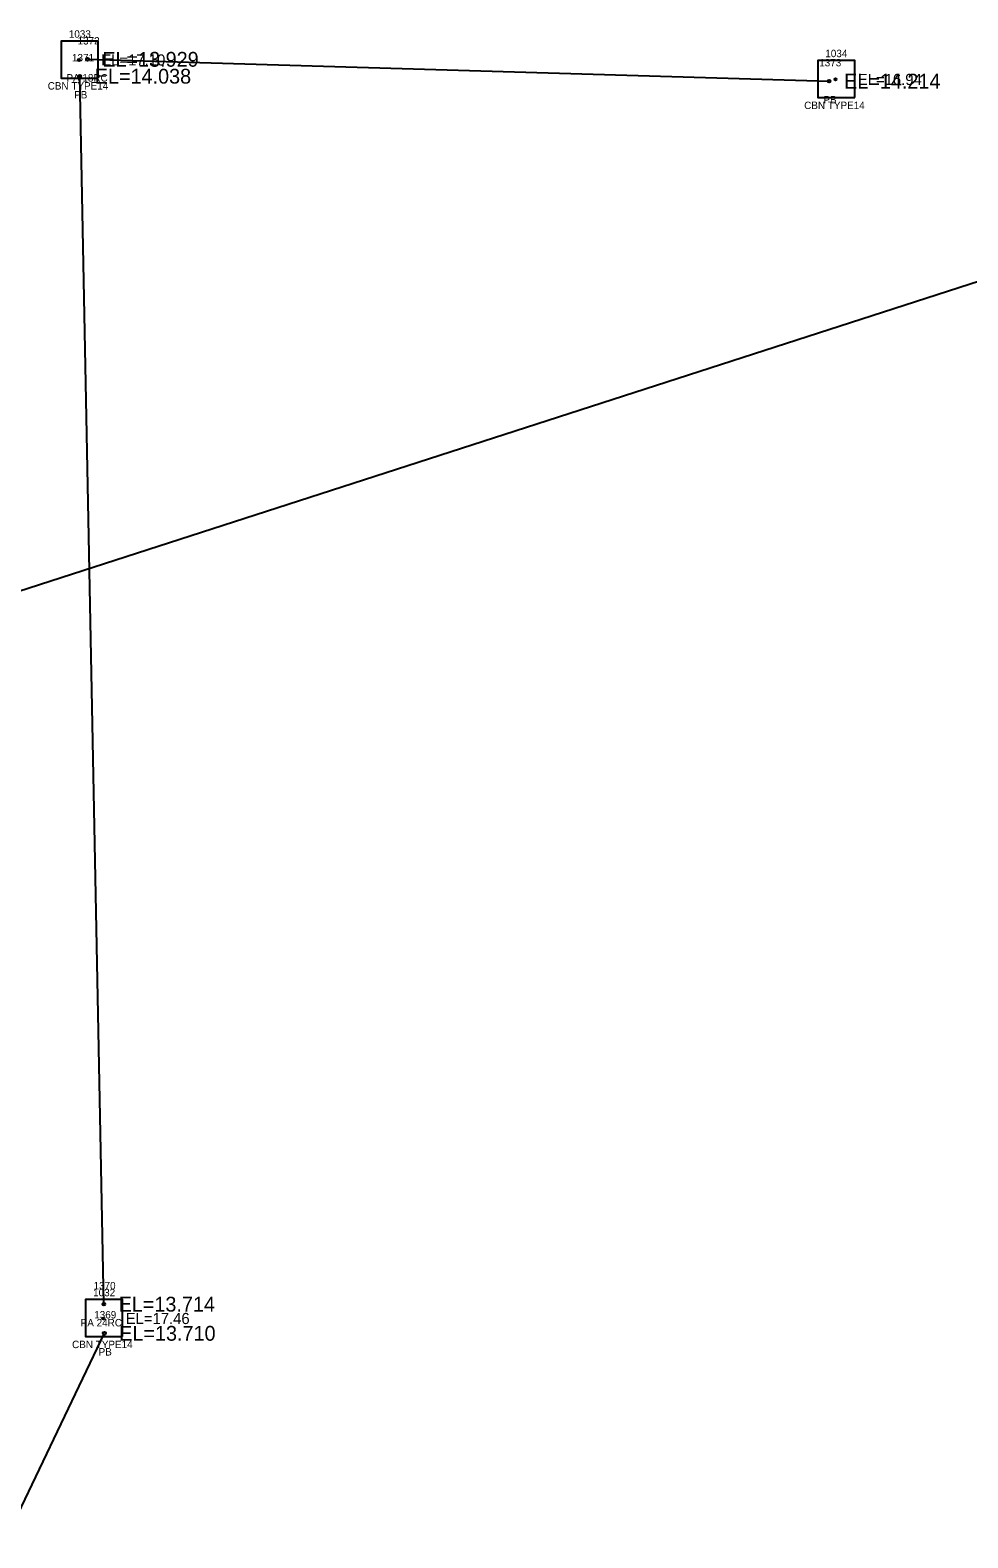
# Model space of a CAD drawing. Extents: x 2072307 to 2072993, y 127574 to 129736.
# Drawn here: x 2072496.8 to 2072623.4, y 129052.1 to 129255.6 of the extents above; entities that cross this region are included whole.
import ezdxf

# ---------------------------------------------------------------- set-up
doc = ezdxf.new("R2010")
doc.units = 0
for name, color, linetype in [('RD_EX_DR_Inlet', 7, 'Continuous'), ('RD_EX_DR_Inlet_txCode', 7, 'Continuous'), ('RD_EX_DR_Pipe', 7, 'Continuous'), ('RD_EX_DR_Pipe_txCode', 7, 'Continuous'), ('RD_EX_TX_DR_Inlet_ELEV', 7, 'Continuous'), ('RD_SMD_Locator', 7, 'Continuous'), ('RD_TX_Pipe_ElevEX', 7, 'Continuous')]:
    doc.layers.add(name, color=color, linetype=linetype)

msp = doc.modelspace()

# ---------------------------------------------------------------- linework, layer by layer
at = {"layer": 'RD_EX_DR_Inlet'}
for p, q in [((2072505.99, 129249.09), (2072505.99, 129254.09)), ((2072608.13, 129246.45), (2072608.13, 129251.45)), ((2072509.28, 129079.26), (2072509.28, 129084.26))]:
    msp.add_line(p, q, dxfattribs=at)
for points in [[(2072505.99, 129249.09), (2072505.99, 129254.09), (2072500.99, 129254.09), (2072500.99, 129249.09)], [(2072608.13, 129246.45), (2072608.13, 129251.45), (2072603.13, 129251.45), (2072603.13, 129246.45)], [(2072509.28, 129079.26), (2072509.28, 129084.26), (2072504.28, 129084.26), (2072504.28, 129079.26)]]:
    msp.add_lwpolyline(points, close=True, dxfattribs=at)
at = {"layer": 'RD_EX_DR_Pipe'}
for p, q in [((2072504.54, 129251.62), (2072604.69, 129248.67)), ((2072506.74, 129083.64), (2072503.52, 129249.34)), ((2072413.78, 129153.52), (2072668.09, 129235.65)), ((2072442.84, 128946.09), (2072506.82, 129079.71))]:
    msp.add_line(p, q, dxfattribs=at)
at = {"layer": 'RD_SMD_Locator'}
for centre, radius in [((2072503.4, 129251.54), 0.15), ((2072504.54, 129251.62), 0.2), ((2072503.52, 129249.34), 0.2), ((2072604.69, 129248.67), 0.2), ((2072605.54, 129248.91), 0.15), ((2072506.74, 129083.64), 0.2), ((2072506.69, 129081.71), 0.15), ((2072506.82, 129079.71), 0.2)]:
    msp.add_circle(centre, radius, dxfattribs=at)

# ---------------------------------------------------------------- texts
at = {"layer": 'RD_EX_DR_Inlet_txCode'}
for s, p in [('1033', (2072502.02, 129254.54)), ('1034', (2072604.16, 129251.91)), ('CBN TYPE14', (2072499.17, 129247.54)), ('CBN TYPE14', (2072601.31, 129244.91)), ('1032', (2072505.3, 129084.71)), ('CBN TYPE14', (2072502.46, 129077.71))]:
    msp.add_text(s, height=1, dxfattribs=at).set_placement(p)
at = {"layer": 'RD_EX_DR_Pipe_txCode'}
for s, p in [('1372', (2072503.2, 129253.62)), ('1371', (2072502.45, 129251.34)), ('1373', (2072603.34, 129250.67)), ('PA 18RC', (2072501.7, 129248.62)), ('PB', (2072502.74, 129246.34)), ('PB', (2072603.91, 129245.67)), ('1370', (2072505.36, 129085.64)), ('1369', (2072505.45, 129081.71)), ('PA 24RC', (2072503.62, 129080.64)), ('PB', (2072506.04, 129076.71))]:
    msp.add_text(s, height=1, dxfattribs=at).set_placement(p)
at = {"layer": 'RD_EX_TX_DR_Inlet_ELEV'}
for s, p in [('EL=17.10', (2072506.4, 129250.79)), ('EL=16.94', (2072608.54, 129248.16)), ('EL=17.46', (2072509.69, 129080.96))]:
    msp.add_text(s, height=1.5, dxfattribs=at).set_placement(p)
at = {"layer": 'RD_TX_Pipe_ElevEX'}
for s, p in [('EL=13.929', (2072506.54, 129250.62)), ('EL=14.038', (2072505.52, 129248.34)), ('EL=14.214', (2072606.69, 129247.67)), ('EL=13.714', (2072508.74, 129082.64)), ('EL=13.710', (2072508.82, 129078.71))]:
    msp.add_text(s, height=2, dxfattribs=at).set_placement(p)

doc.saveas('drawing.dxf')
